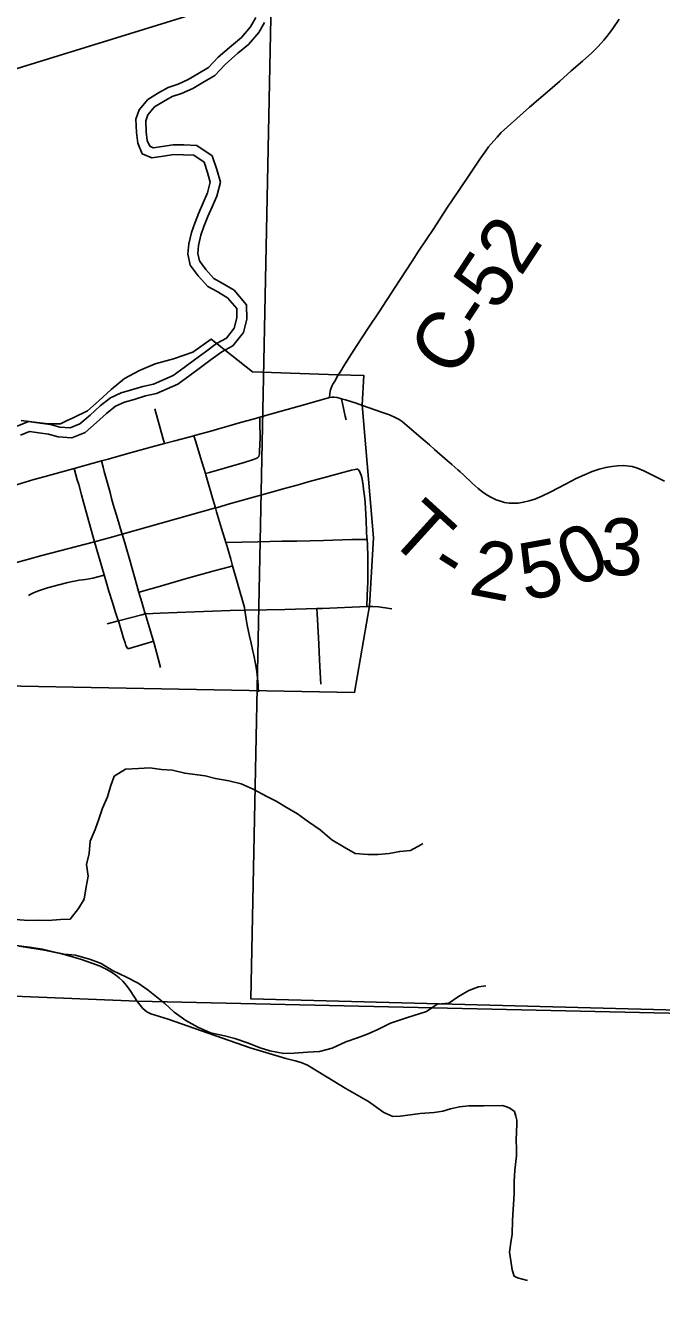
# Model space of a CAD drawing. Extents: x 0 to 34, y 0 to 22.
# Drawn here: x 28.896 to 29.531, y 18.296 to 19.567 of the extents above; entities that cross this region are included whole.
import ezdxf

# ---------------------------------------------------------------- set-up
doc = ezdxf.new("R2010")
doc.units = 0
for name, color, linetype in [('GM_X_City_Street', 7, 'Continuous'), ('GM_X_Corporation', 7, 'Continuous'), ('GM_X_County_Road', 7, 'Continuous'), ('GM_X_County_Road_Text', 7, 'Continuous'), ('GM_X_Major_River', 7, 'Continuous'), ('GM_X_Minor_River', 7, 'Continuous'), ('GM_X_Rail_Line', 7, 'Continuous'), ('GM_X_Township_Road', 7, 'Continuous'), ('GM_X_Township_Road_Text', 7, 'Continuous')]:
    doc.layers.add(name, color=color, linetype=linetype)

msp = doc.modelspace()

# ---------------------------------------------------------------- linework, layer by layer
at = {"layer": 'GM_X_City_Street'}
for points in [[(29.1994, 19.1963), (29.1997, 19.2), (29.1998, 19.202), (29.2001, 19.2039), (29.2008, 19.2055), (29.2017, 19.2075), (29.2026, 19.2095), (29.2044, 19.2126), (29.2077, 19.2182)], [(28.8868, 19.109), (28.9041, 19.1142), (28.9154, 19.1174), (28.9406, 19.1242), (28.9443, 19.1252), (28.9716, 19.1328), (28.9783, 19.1347), (28.9956, 19.1396), (29.0208, 19.1466), (29.0344, 19.1502), (29.0448, 19.153), (29.0639, 19.1579), (29.0646, 19.1581), (29.0809, 19.1627), (29.0873, 19.1646), (29.099, 19.1678), (29.1103, 19.1711), (29.1229, 19.1745), (29.1297, 19.1764), (29.151, 19.1824), (29.1689, 19.1874), (29.1958, 19.1953), (29.1994, 19.1963), (29.2015, 19.1966), (29.2039, 19.1965), (29.2068, 19.1961), (29.2112, 19.1948), (29.2151, 19.1937), (29.2258, 19.1904), (29.2321, 19.1882)], [(29.2158, 19.1738), (29.2149, 19.1774), (29.2122, 19.1903), (29.2112, 19.1948)], [(29.0344, 19.1502), (29.0328, 19.156), (29.0249, 19.1848)], [(29.0753, 19.1202), (29.0793, 19.1213), (29.114, 19.1313), (29.1233, 19.1342), (29.125, 19.1349), (29.1266, 19.1357), (29.1278, 19.1364), (29.1286, 19.1373), (29.1291, 19.1386), (29.1292, 19.1398), (29.1294, 19.1421), (29.1298, 19.1494), (29.1301, 19.1562), (29.1298, 19.1711), (29.1297, 19.1764)], [(29.1283, 18.9025), (29.128, 18.9078), (29.1279, 18.9102), (29.1278, 18.912), (29.1274, 18.9163), (29.1266, 18.9224), (29.1254, 18.9304), (29.1237, 18.9389), (29.1228, 18.9431), (29.121, 18.9509), (29.1194, 18.9581), (29.117, 18.9689), (29.116, 18.975), (29.1146, 18.984), (29.1142, 18.9866), (29.1074, 19.0109), (29.1025, 19.0281), (29.1006, 19.0347), (29.0959, 19.0507), (29.0956, 19.0516), (29.0946, 19.0548), (29.0914, 19.0655), (29.0865, 19.0821), (29.0854, 19.0859), (29.0829, 19.0947), (29.0756, 19.1191), (29.0753, 19.1202), (29.0705, 19.1363), (29.0658, 19.1518), (29.0639, 19.1579)], [(28.9977, 18.9457), (28.9972, 18.9462), (28.996, 18.9486), (28.9951, 18.9512), (28.9937, 18.956), (28.9884, 18.9732), (28.9879, 18.9747), (28.9853, 18.9824), (28.9824, 18.9916), (28.9789, 19.003), (28.9743, 19.019), (28.9647, 19.0522), (28.9538, 19.0905), (28.9517, 19.099), (28.9488, 19.1092), (28.9474, 19.1139), (28.946, 19.1191), (28.9443, 19.1252)], [(29.0306, 18.9268), (29.0282, 18.9357), (29.0243, 18.9506), (29.0236, 18.9528), (29.0219, 18.9583), (29.0205, 18.963), (29.0163, 18.9772), (29.0154, 18.9801), (29.015, 18.9813), (29.0133, 18.9872), (29.0119, 18.9918), (29.0089, 19.0016), (29.0068, 19.0089), (29.0038, 19.0195), (28.9998, 19.0339), (28.9962, 19.0464), (28.9948, 19.0511), (28.9922, 19.0598), (28.9916, 19.0617), (28.9874, 19.0753), (28.9832, 19.0895), (28.9817, 19.0955), (28.9802, 19.1015), (28.9744, 19.1224), (28.9733, 19.1265), (28.9716, 19.1328)], [(28.8448, 19.02), (28.8978, 19.0346), (28.912, 19.0386), (28.9647, 19.0522), (28.9829, 19.0572), (28.9922, 19.0598), (29.0854, 19.0859), (29.0875, 19.0864), (29.0994, 19.09), (29.1412, 19.1017), (29.1544, 19.1053), (29.1693, 19.1094), (29.1781, 19.1119), (29.1942, 19.1164), (29.2127, 19.1214), (29.2175, 19.1226), (29.2211, 19.1235), (29.2247, 19.1242), (29.2262, 19.1245), (29.2276, 19.1245)], [(29.2365, 18.9876), (29.237, 18.9986), (29.2374, 19.0123), (29.2375, 19.0276), (29.2374, 19.0417), (29.2373, 19.044), (29.2371, 19.0494), (29.2367, 19.0543), (29.2366, 19.056), (29.2363, 19.0621), (29.2357, 19.0738), (29.2351, 19.0855), (29.2347, 19.0916), (29.2341, 19.0976), (29.2333, 19.1047), (29.2328, 19.1084), (29.2322, 19.1126), (29.2315, 19.1163), (29.2308, 19.1187), (29.2299, 19.121), (29.2291, 19.1227), (29.2283, 19.124), (29.2276, 19.1245)], [(29.0956, 19.0516), (29.1277, 19.0521), (29.1517, 19.0526), (29.1665, 19.0528), (29.1934, 19.0533), (29.2217, 19.0543), (29.2367, 19.0543)], [(29.0089, 19.0016), (29.0106, 19.0022), (29.0161, 19.0038), (29.0281, 19.0071), (29.0566, 19.0154), (29.0841, 19.023), (29.0993, 19.0272), (29.1025, 19.0281)], [(28.8988, 18.9987), (28.9004, 18.9995), (28.903, 19.0007), (28.9052, 19.0017), (28.9078, 19.0027), (28.9106, 19.0037), (28.9176, 19.0061), (28.9289, 19.0093), (28.9379, 19.0115), (28.9427, 19.0126), (28.9446, 19.0129), (28.9494, 19.0137), (28.9531, 19.0142), (28.9556, 19.0146), (28.9628, 19.016), (28.9728, 19.0186), (28.9743, 19.019)], [(28.9773, 18.9703), (28.9884, 18.9732), (29.0119, 18.9792), (29.0154, 18.9801), (29.0303, 18.981), (29.0471, 18.9817), (29.1001, 18.9837), (29.1146, 18.984), (29.1368, 18.9842), (29.1545, 18.9846), (29.1759, 18.9852), (29.1866, 18.9855), (29.1921, 18.9856), (29.2365, 18.9876)], [(29.1906, 18.9101), (29.1896, 18.9278), (29.1881, 18.9567), (29.1868, 18.9803), (29.1866, 18.9855)], [(28.9977, 18.9457), (28.9983, 18.9455), (28.9991, 18.9456), (29.0204, 18.9518), (29.0236, 18.9528)]]:
    msp.add_lwpolyline(points, dxfattribs=at)
at = {"layer": 'GM_X_Corporation'}
for points in [[(26.6535, 14.621), (27.01, 14.6164), (27.046, 14.6155), (27.043, 14.755), (27.052, 15.403), (27.0676, 16.5549), (27.0694, 16.6556), (27.0775, 16.888), (27.0944, 18.0731), (27.1039, 18.5696), (27.1064, 18.6537), (27.3971, 18.6436), (28.3421, 18.6121), (28.7772, 18.6028), (29.0074, 18.5935), (29.6561, 18.5791), (29.6772, 18.5786), (30.101, 18.5701), (30.3167, 18.565), (30.3167, 20.9), (23.5167, 20.9)], [(26.3378, 16.673), (27.0694, 16.6556), (27.0775, 16.888), (27.0944, 18.0731), (27.1039, 18.5696), (27.1064, 18.6537), (27.3971, 18.6436), (28.3421, 18.6121), (28.7772, 18.6028), (29.0074, 18.5935), (29.6561, 18.5791), (29.6772, 18.5786), (30.101, 18.5701), (30.3167, 18.565), (30.3167, 20.9), (25.1014, 20.9)], [(28.8914, 19.1732), (28.9019, 19.1719), (28.9183, 19.1699), (28.9308, 19.1699), (28.9373, 19.1732), (28.9432, 19.1758), (28.9577, 19.183), (28.9688, 19.1929), (28.9813, 19.204), (28.9944, 19.2152), (29.0095, 19.2231), (29.0253, 19.2296), (29.0436, 19.2349), (29.0627, 19.2414), (29.081, 19.2545), (29.1225, 19.2219), (29.2075, 19.2187), (29.2336, 19.2181), (29.2319, 19.1887), (29.2431, 19.056), (29.2393, 18.9881), (29.2241, 18.9016), (28.6276, 18.9129)], [(23.5167, 14.1), (30.3167, 14.1), (30.3167, 18.565), (30.101, 18.5701), (29.6772, 18.5786), (29.6561, 18.5791), (29.0074, 18.5935), (28.7772, 18.6028), (28.3421, 18.6121), (27.3971, 18.6436), (27.1064, 18.6537), (27.1039, 18.5696), (27.0944, 18.0731), (27.0775, 16.888), (27.0694, 16.6556), (27.0676, 16.5549), (27.052, 15.403), (27.043, 14.755), (27.046, 14.6155), (27.01, 14.6164), (26.6535, 14.621)], [(30.3167, 14.5373), (30.3167, 18.565), (30.101, 18.5701), (29.6772, 18.5786), (29.6561, 18.5791), (29.0074, 18.5935), (28.7772, 18.6028), (28.3421, 18.6121), (27.3971, 18.6436), (27.1064, 18.6537), (27.1039, 18.5696), (27.0944, 18.0731)]]:
    msp.add_lwpolyline(points, dxfattribs=at)
msp.add_lwpolyline([(30.1599, 19.5824), (30.1382, 18.5689), (29.1208, 18.5959), (29.1414, 19.6082)], close=True, dxfattribs=at)
at = {"layer": 'GM_X_County_Road'}
msp.add_lwpolyline([(29.2077, 19.2182), (29.2099, 19.2215), (29.2142, 19.2286), (29.226, 19.2469), (29.2377, 19.2652), (29.2487, 19.2818), (29.2641, 19.3052), (29.2818, 19.3322), (29.2882, 19.3421), (29.3034, 19.3649), (29.3165, 19.3852), (29.3291, 19.4037), (29.3395, 19.4192), (29.3495, 19.4342), (29.3559, 19.4433), (29.3581, 19.4463), (29.3632, 19.4525), (29.3665, 19.4561), (29.3708, 19.4605), (29.3799, 19.4689), (29.399, 19.4858), (29.4192, 19.5033), (29.4291, 19.5118), (29.4407, 19.5221), (29.452, 19.5319), (29.4612, 19.5403), (29.4674, 19.5465), (29.4733, 19.5529), (29.4776, 19.5583), (29.482, 19.5644), (29.4886, 19.5738)], dxfattribs=at)
at = {"layer": 'GM_X_Major_River'}
for points in [[(28.8873, 19.1676), (28.8986, 19.1723), (28.9103, 19.1705), (28.9205, 19.1691), (28.93, 19.1665), (28.9402, 19.1659), (28.95, 19.1698), (28.9601, 19.1786), (28.9703, 19.1878), (28.9804, 19.1959), (28.9913, 19.2009), (29.0015, 19.2037), (29.0128, 19.2072), (29.0234, 19.2096), (29.043, 19.2181), (29.0542, 19.2262), (29.0644, 19.2339), (29.0753, 19.2419), (29.0865, 19.25), (29.0963, 19.2554), (29.1042, 19.2654), (29.1067, 19.2756), (29.1066, 19.2851), (29.0975, 19.2956), (29.0872, 19.3019), (29.0777, 19.3071), (29.0682, 19.3176), (29.0601, 19.3282), (29.0578, 19.3395), (29.0588, 19.3494), (29.0614, 19.3608), (29.0647, 19.3703), (29.0688, 19.3805), (29.0732, 19.3904), (29.0773, 19.4003), (29.0802, 19.411), (29.0775, 19.4208), (29.074, 19.431), (29.0637, 19.4381), (29.0535, 19.4383), (29.0437, 19.4386), (29.0335, 19.437), (29.0218, 19.4354), (29.0123, 19.4394), (29.0077, 19.45), (29.0064, 19.4606), (29.006, 19.4738), (29.0093, 19.4833), (29.0179, 19.4937), (29.0284, 19.5002), (29.0382, 19.5056), (29.048, 19.5088), (29.0582, 19.5134), (29.0679, 19.5192), (29.0785, 19.5254), (29.0882, 19.5357), (29.1013, 19.5472), (29.1115, 19.5556), (29.1204, 19.566), (29.1257, 19.5755)], [(28.8907, 19.1584), (28.8998, 19.1621), (28.9089, 19.1608), (28.9186, 19.1594), (28.9284, 19.1568), (28.9418, 19.1559), (28.9552, 19.1613), (28.9667, 19.1712), (28.9766, 19.1803), (28.9856, 19.1874), (28.9947, 19.1916), (29.0043, 19.1942), (29.0154, 19.1977), (29.0265, 19.2002), (29.0478, 19.2095), (29.0601, 19.2183), (29.0703, 19.226), (29.0811, 19.234), (29.0918, 19.2417), (29.1028, 19.2478), (29.1132, 19.2609), (29.1166, 19.2744), (29.1164, 19.2888), (29.1039, 19.3032), (29.0922, 19.3104), (29.0839, 19.315), (29.0757, 19.3239), (29.0693, 19.3324), (29.0677, 19.34), (29.0685, 19.3478), (29.0708, 19.3581), (29.0739, 19.3668), (29.0778, 19.3767), (29.0822, 19.3865), (29.0866, 19.3971), (29.0904, 19.411), (29.0869, 19.4237), (29.0822, 19.4372), (29.0669, 19.4478), (29.0538, 19.4482), (29.043, 19.4485), (29.032, 19.4467), (29.0231, 19.4455), (29.0197, 19.4469), (29.0173, 19.4526), (29.0163, 19.4613), (29.0158, 19.4724), (29.018, 19.4784), (29.0244, 19.4862), (29.0334, 19.4917), (29.0421, 19.4966), (29.0515, 19.4996), (29.0627, 19.5047), (29.0729, 19.5107), (29.0847, 19.5176), (29.095, 19.5286), (29.1077, 19.5397), (29.1184, 19.5486), (29.1286, 19.5603), (29.1342, 19.5706)], [(28.8907, 19.1584), (28.8998, 19.1621), (28.9089, 19.1608), (28.9186, 19.1594), (28.9284, 19.1568), (28.9418, 19.1559), (28.9552, 19.1613), (28.9667, 19.1712), (28.9766, 19.1803), (28.9856, 19.1874), (28.9947, 19.1916), (29.0043, 19.1942), (29.0154, 19.1977), (29.0265, 19.2002), (29.0478, 19.2095), (29.0601, 19.2183), (29.0703, 19.226), (29.0811, 19.234), (29.0918, 19.2417), (29.1028, 19.2478), (29.1132, 19.2609), (29.1166, 19.2744), (29.1164, 19.2888), (29.1039, 19.3032), (29.0922, 19.3104), (29.0839, 19.315), (29.0757, 19.3239), (29.0693, 19.3324), (29.0677, 19.34), (29.0685, 19.3478), (29.0708, 19.3581), (29.0739, 19.3668), (29.0778, 19.3767), (29.0822, 19.3865), (29.0866, 19.3971), (29.0904, 19.411), (29.0869, 19.4237), (29.0822, 19.4372), (29.0669, 19.4478), (29.0538, 19.4482), (29.043, 19.4485), (29.032, 19.4467), (29.0231, 19.4455), (29.0197, 19.4469), (29.0173, 19.4526), (29.0163, 19.4613), (29.0158, 19.4724), (29.018, 19.4784), (29.0244, 19.4862), (29.0334, 19.4917), (29.0421, 19.4966), (29.0515, 19.4996), (29.0627, 19.5047), (29.0729, 19.5107), (29.0847, 19.5176), (29.095, 19.5286), (29.1077, 19.5397), (29.1184, 19.5486), (29.1286, 19.5603), (29.1342, 19.5706)]]:
    msp.add_lwpolyline(points, dxfattribs=at)
at = {"layer": 'GM_X_Minor_River'}
for points in [[(28.8859, 18.6751), (28.8984, 18.6741), (28.9082, 18.6745), (28.9184, 18.6743), (28.9305, 18.6752), (28.9403, 18.6756), (28.9486, 18.686), (28.9541, 18.6955), (28.9563, 18.7076), (28.9581, 18.7183), (28.9565, 18.73), (28.9594, 18.741), (28.9601, 18.7535), (28.9653, 18.7649), (28.9689, 18.7752), (28.9726, 18.7862), (28.9774, 18.7976), (28.9804, 18.8079), (28.9841, 18.8182), (28.9954, 18.8251), (29.0086, 18.826), (29.0199, 18.8265), (29.0316, 18.8247), (29.0426, 18.8241), (29.0547, 18.8212), (29.0752, 18.8184), (29.0854, 18.8158), (29.0986, 18.8137), (29.1112, 18.8104), (29.1229, 18.8052), (29.1366, 18.7978), (29.1461, 18.7934), (29.1571, 18.7866), (29.1674, 18.7807), (29.1784, 18.7725), (29.1898, 18.7646), (29.2016, 18.7545), (29.2138, 18.7475), (29.2248, 18.7411), (29.2376, 18.7401), (29.2479, 18.7399), (29.2588, 18.7411), (29.2694, 18.7431), (29.28, 18.744), (29.2905, 18.7498), (29.2924, 18.7509)], [(28.8865, 18.6493), (28.8994, 18.6476), (28.9126, 18.6454), (28.9232, 18.6429), (28.9342, 18.6407), (28.9456, 18.6397), (28.9607, 18.6353), (28.9713, 18.6313), (28.9827, 18.6242), (28.9964, 18.6175), (29.0082, 18.6116), (29.0181, 18.6045), (29.0348, 18.5912)], [(29.296, 18.5834), (29.3066, 18.5905), (29.3183, 18.5917), (29.3281, 18.5983), (29.3382, 18.6044), (29.348, 18.6079), (29.3552, 18.6088)], [(29.0348, 18.5912), (29.0442, 18.5825), (29.0559, 18.5742), (29.0676, 18.5677), (29.0805, 18.562), (29.0945, 18.5589), (29.1047, 18.5563), (29.1175, 18.5521), (29.13, 18.5471), (29.1398, 18.5441), (29.1538, 18.5414), (29.164, 18.5418), (29.1772, 18.5429), (29.1893, 18.5433), (29.2018, 18.5467), (29.2155, 18.5531), (29.2272, 18.5572), (29.2378, 18.561), (29.2476, 18.5652), (29.2601, 18.5716), (29.2762, 18.5771), (29.296, 18.5834)]]:
    msp.add_lwpolyline(points, dxfattribs=at)
at = {"layer": 'GM_X_Rail_Line'}
msp.add_lwpolyline([(28.8515, 19.5134), (29.4007, 19.6833), (29.491, 19.707), (29.5813, 19.7244), (29.9149, 19.7778), (30.0206, 19.7932), (30.1151, 19.8044), (30.1859, 19.8065), (30.2475, 19.8096), (30.2867, 19.817), (30.3167, 19.8284)], dxfattribs=at)
at = {"layer": 'GM_X_Township_Road'}
for points in [[(29.299, 19.149), (29.2883, 19.158), (29.2717, 19.1721), (29.2687, 19.1742), (29.2649, 19.1763), (29.2592, 19.1787), (29.2522, 19.1813), (29.2389, 19.1858), (29.2321, 19.1882)], [(29.5336, 19.1128), (29.5297, 19.1147), (29.5237, 19.1178), (29.5132, 19.1231), (29.5069, 19.1256), (29.5016, 19.1272), (29.4985, 19.1277), (29.493, 19.1283), (29.4868, 19.1281), (29.4813, 19.1274), (29.4751, 19.1263), (29.4685, 19.1245), (29.4615, 19.1222), (29.454, 19.1191), (29.4456, 19.1152), (29.4356, 19.11), (29.4197, 19.1016), (29.4113, 19.0976), (29.4044, 19.0948), (29.3985, 19.0929), (29.393, 19.0916), (29.3875, 19.0908), (29.3838, 19.0906), (29.3788, 19.0907), (29.3739, 19.0915), (29.3709, 19.0922), (29.3656, 19.0941), (29.3611, 19.0962), (29.3568, 19.0987), (29.3522, 19.1018), (29.3478, 19.1052), (29.3418, 19.1106), (29.3329, 19.119), (29.3297, 19.1219), (29.3274, 19.124), (29.3214, 19.1294), (29.3143, 19.1354), (29.304, 19.1443), (29.299, 19.149)], [(29.2365, 18.9876), (29.2395, 18.9876), (29.2425, 18.9876), (29.2481, 18.9872), (29.2549, 18.9863), (29.2615, 18.9852)], [(28.889, 18.6487), (28.9019, 18.6464), (28.9147, 18.6444), (28.9239, 18.6426), (28.9305, 18.6412), (28.9402, 18.6387), (28.9515, 18.6353), (28.962, 18.6317), (28.9701, 18.6285), (28.9763, 18.6255), (28.9817, 18.6225), (28.9858, 18.6197), (28.9892, 18.6169), (28.9928, 18.6135), (28.9965, 18.6093), (29.0002, 18.6043), (29.0076, 18.593)], [(29.3231, 18.487), (29.3201, 18.4863), (29.3124, 18.4838), (29.3038, 18.4824), (29.2899, 18.4814), (29.2774, 18.4798), (29.2698, 18.4789), (29.2625, 18.4784), (29.2536, 18.4826), (29.2383, 18.4936), (29.2148, 18.5069), (29.1774, 18.5297), (29.1708, 18.5324), (29.165, 18.5341), (29.1558, 18.5364), (29.1389, 18.5413), (29.12, 18.5472), (29.0714, 18.564), (29.038, 18.5758), (29.0207, 18.5809), (29.0167, 18.583), (29.0129, 18.5862), (29.0076, 18.593)], [(29.397, 18.315), (29.387, 18.3175), (29.3836, 18.3191), (29.3818, 18.3255), (29.3803, 18.3345), (29.3789, 18.343), (29.3806, 18.3552), (29.3815, 18.3607), (29.3819, 18.3749), (29.3837, 18.4015), (29.3837, 18.4136), (29.3843, 18.4249), (29.3858, 18.4392), (29.3858, 18.4463), (29.3856, 18.4549), (29.3864, 18.4712), (29.3864, 18.475), (29.3854, 18.4789), (29.3841, 18.4834), (29.3794, 18.4867), (29.3754, 18.4885), (29.3716, 18.4895), (29.3533, 18.4893), (29.3383, 18.4891), (29.3289, 18.4883), (29.3231, 18.487)]]:
    msp.add_lwpolyline(points, dxfattribs=at)

# ---------------------------------------------------------------- texts
at = {"layer": 'GM_X_County_Road_Text'}
msp.add_text('C-52', height=0.05682, rotation=56.6824, dxfattribs=at).set_placement((29.323, 19.2137))
at = {"layer": 'GM_X_Township_Road_Text'}
for s, rotation, p in [('T', 317.7541, (29.2558, 19.0561)), ('3', 359.3443, (29.4695, 19.019)), ('0', 26.3936, (29.445, 19.0051)), ('2', 349.1835, (29.337, 19.0001)), ('5', 10.1897, (29.394, 18.9934)), ('-', 327.7845, (29.2959, 19.0209))]:
    msp.add_text(s, height=0.0568, rotation=rotation, dxfattribs=at).set_placement(p)

doc.saveas('drawing.dxf')
